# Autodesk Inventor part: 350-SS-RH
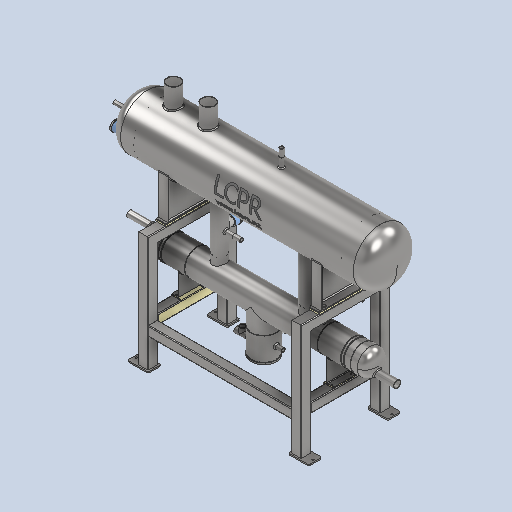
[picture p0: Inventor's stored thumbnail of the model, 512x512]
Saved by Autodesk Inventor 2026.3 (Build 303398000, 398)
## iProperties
Created: 2026-05
Part Number: 350-SS-RH
Material: Generic
Document SubType Name: Modeling
Designer: rva
Density: 1 g/cm^3
Appearance: Default
Author: rva
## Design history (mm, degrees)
derived "350-SS-RH.iam"
body "Solid1"
node "LPR-350-Frame Assembly.iam:1::LCPR-SS-350-135 x 85 Frame Foo"
node "LPR-350-Frame Assembly.iam:1::LCPR-SS-350-135 x 85 Frame Foo"
node "LPR-350-Frame Assembly.iam:1::LCPR-SS-350-135 x 85 Frame Foo"
node "LPR-350-Frame Assembly.iam:1::LCPR-SS-350-135 x 85 Frame Foo"
node "Sub-150-75-1171-30-40-32-SS-RH.iam:1::ISO 5251 Equal Tee DN1"
node "Sub-150-75-1171-30-40-32-SS-RH.iam:1::150-30-SS-Hole Sub Coo"
node "Sub-150-75-1171-30-40-32-SS-RH.iam:1::150-30-SS-Hole Sub Coo"
node "Sub-150-75-1171-30-40-32-SS-RH.iam:1::150 mm-SS- Subcooler L"
node "Sub-150-75-1171-30-40-32-SS-RH.iam:1::LCPR-150-SS-Blank Plat"
node "Sub-150-75-1171-30-40-32-SS-RH.iam:1::150 mm-SS- Subcooler L"
node "Sub-150-75-1171-30-40-32-SS-RH.iam:1::1-2 Inch NPT Socket - "
node "Sub-150-75-1171-30-40-32-SS-RH.iam:1::1-2 Inch NPT Socket - "
node "Sub-150-75-1171-30-40-32-SS-RH.iam:1::1-2 Inch NPT Socket - "
node "Sub-150-75-1171-30-40-32-SS-RH.iam:1::H1100-R.ipt:1"
node "Sub-150-75-1171-30-40-32-SS-RH.iam:1::H1100-R.ipt:2"
node "Sub-150-75-1171-30-40-32-SS-RH.iam:1::Welds"
node "Nylon Heat Tranfer Spacer 348x65.ipt:1"
node "Nylon Heat Tranfer Spacer 348x65.ipt:2"
node "AS 1111 - Metric M10 x 100:1"
node "AS 1112 (4) - Metric M10:1"
node "AS 1237 (4.1) 10 mm:1"
node "AS 1237 (4.1) 10 mm:2"
node "AS 1111 - Metric M10 x 100:2"
node "AS 1112 (4) - Metric M10:2"
node "AS 1237 (4.1) 10 mm:3"
node "AS 1237 (4.1) 10 mm:4"
node "AS 1111 - Metric M10 x 100:3"
node "AS 1112 (4) - Metric M10:3"
node "AS 1237 (4.1) 10 mm:5"
node "AS 1237 (4.1) 10 mm:6"
node "AS 1111 - Metric M10 x 100:4"
node "AS 1112 (4) - Metric M10:4"
node "AS 1237 (4.1) 10 mm:7"
node "AS 1237 (4.1) 10 mm:8"
node "350-SS-SHELL-WELD.iam:1::LCPR-LOGO.ipt:1"
node "350-SS-SHELL-WELD.iam:1::LCPR-SS-350-Leg Assembly.iam:1::Wel"
node "350-SS-SHELL-WELD.iam:1::LCPR-SS-350-Leg Assembly.iam:2::Wel"
node "350-SS-SHELL-WELD.iam:1::350 mm-SS- Dome End Cap.ipt:1"
node "350-SS-SHELL-WELD.iam:1::350 mm-SS- Dome End Cap.ipt:2"
node "350-SS-SHELL-WELD.iam:1::H1100-R.ipt:1"
node "350-SS-SHELL-WELD.iam:1::Welds"
node "Nylon Heat Tranfer Spacer 145x65.ipt:1"
node "Nylon Heat Tranfer Spacer 145x65.ipt:2"
node "350-SS-RH.iam_Bodies"
